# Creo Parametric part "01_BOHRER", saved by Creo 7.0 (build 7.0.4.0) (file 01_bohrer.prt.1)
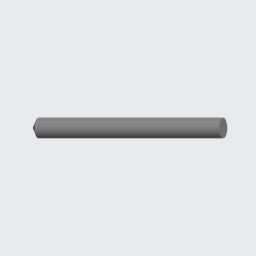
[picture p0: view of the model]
Units: millimeter Kilogram Sec (mmKs); MM, KILOGRAM, SECS
Materials in the file: S235JRG2

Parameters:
  PTC_MATERIAL_NAME = "S235JRG2"
  BENENNUNG = "XXX"
  DATUM = "XX.XX.XX"
  ERSTELLER = "ARINDA"
  TEILETYP = "Fertigungsteil"
  SELECT_EN_NAME = "S235JRG2"
  SELECT_DIN_NAME = "RSt37-2"
  SELECT_DIN_NUMBER = "1.0038"
  SELECT_ASTM_NAME = "A 283 M Grade 2"
  MATERIAL_GROUP = "ME_ST_Baustahl"
  STANDARD_EN_DELIVERYSPEC = "DIN EN 10025"
  STANDARD_DIN_DELIVERYSPEC = "DIN 17100"

Other parameters: MASSE

Created from: ARINDA-STARTTEIL.PRT

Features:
  1. coordinate system "CS0"
  2. datum plane "DTM1", "T_RECHTS_Y-Z"
  3. datum plane "DTM2", "T_OBEN_X-Z"
  4. datum plane "DTM3", "T_VORNE_X-Y"
  5. datum axis "T_X-ACHSE"
  6. datum axis "A_1"
  7. datum axis "A_2"
  8. revolve "Drehen 1"
  9. group "LOCAL_GROUP"
  10. datum plane "DTM1"
  11. sketch "Skizze 1", "A_2"
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
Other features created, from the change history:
  cut "Spiralförmiges Volumen-Zug-Ke 1" (3 times)
  feature "Drehen 2"
  sketch "Skizze 2"

Other named items: T_BASIC, FRÄSER-SKIZZE, FRÄSER, LEITJURVE, FRAESER, T_Y-ACHSE, T_Z-ACHSE

Layers: 00_STD-ACHSEN, 00_STD-EBENEN, 00_STD-KOORDSYS, 01_ACHSEN, 01_EBENEN, 01_KURVEN, FLAECHEN, KURVENELEMENTE, SAMMELFLÄCHEN, VOLUMENGEOMETRIE

Surfaces: 2 cylinder, 2 cone, 1 plane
